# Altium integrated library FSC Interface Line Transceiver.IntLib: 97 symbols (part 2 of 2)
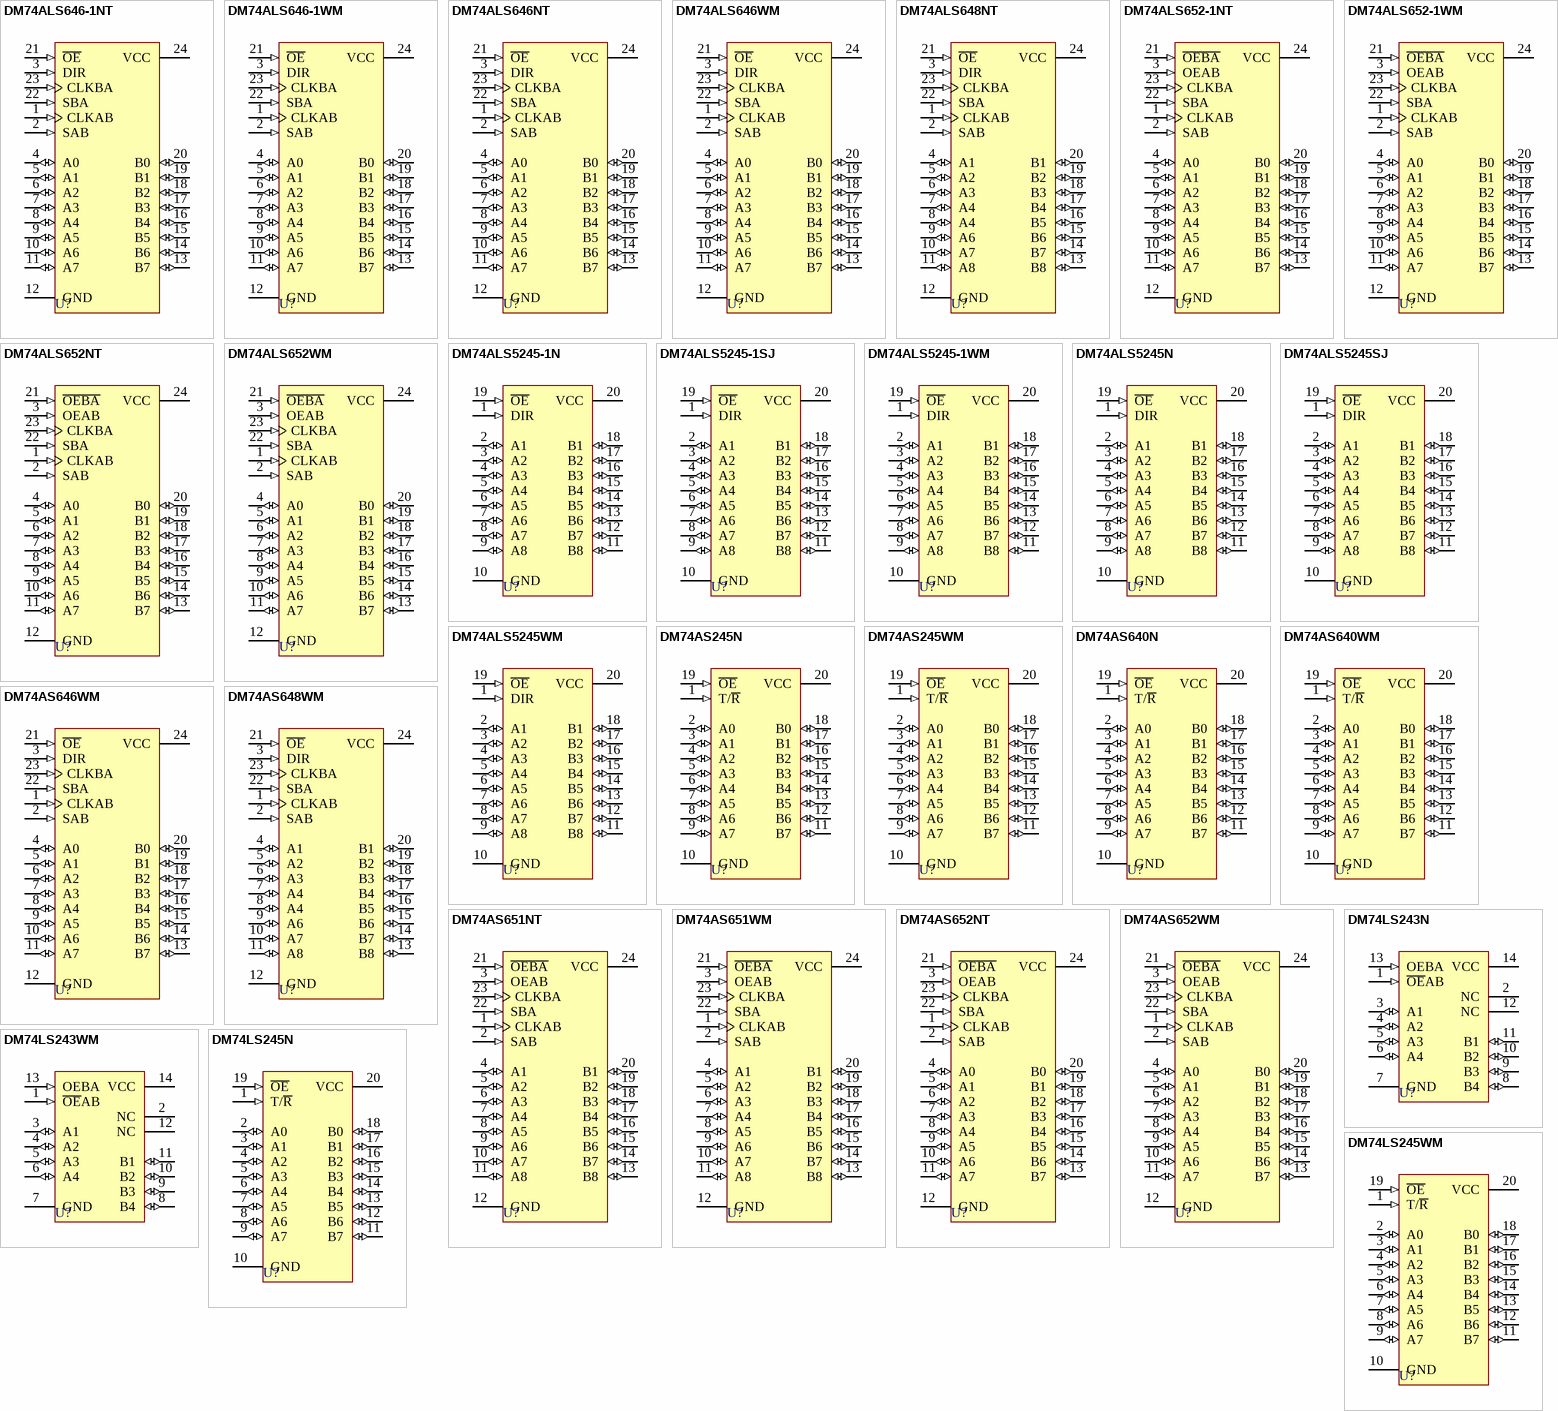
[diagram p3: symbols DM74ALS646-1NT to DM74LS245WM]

## DM74ALS5245N
designator U?
Octal 3-State Transceiver
footprint N20A (DIP; 20 Leads; Row Spacing 7.62 mm; Pitch 2.54 mm)
3D model N20A (DIP; 20 Leads; Row Spacing 7.62 mm; Pitch 2.54 mm)
simulation model 74F245 (SIMCODE)
signal-integrity model DM74ALS5245N
pins: 1 DIR (in), 2 A1 (io), 3 A2 (io), 4 A3 (io), 5 A4 (io), 6 A5 (io), 7 A6 (io), 8 A7 (io), 9 A8 (io), 10 GND (power), 11 B8 (io), 12 B7 (io), 13 B6 (io), 14 B5 (io), 15 B4 (io), 16 B3 (io), 17 B2 (io), 18 B1 (io), 19 ~{OE} (in), 20 VCC (power)

## DM74ALS5245SJ
designator U?
Octal 3-State Transceiver
footprint M20D_N (SOP, 20-Leads, Body 12.6x5.3mm, Pitch 1.27mm, IPC Medium Density)
footprint M20D_L (SOP, 20-Leads, Body 12.6x5.3mm, Pitch 1.27mm, IPC High Density)
footprint M20D_M (SOP, 20-Leads, Body 12.6x5.3mm, Pitch 1.27mm, IPC Low Density)
3D model M20D (20-Pin Small Outline Package 1.27 mm Pitch)
simulation model 74F245 (SIMCODE)
signal-integrity model DM74ALS5245SJ
pins: 1 DIR (in), 2 A1 (io), 3 A2 (io), 4 A3 (io), 5 A4 (io), 6 A5 (io), 7 A6 (io), 8 A7 (io), 9 A8 (io), 10 GND (power), 11 B8 (io), 12 B7 (io), 13 B6 (io), 14 B5 (io), 15 B4 (io), 16 B3 (io), 17 B2 (io), 18 B1 (io), 19 ~{OE} (in), 20 VCC (power)

## DM74ALS5245WM
designator U?
Octal 3-State Transceiver
footprint M20B_N (SOIC, 20-Leads, Body 12.8x7.5mm, Pitch 1.27mm, IPC Medium Density)
footprint M20B_L (SOIC, 20-Leads, Body 12.8x7.5mm, Pitch 1.27mm, IPC High Density)
footprint M20B_M (SOIC, 20-Leads, Body 12.8x7.5mm, Pitch 1.27mm, IPC Low Density)
3D model M20B (20-Pin Small Outline Integrated Circuit 1.27 mm Pitch)
simulation model 74F245 (SIMCODE)
signal-integrity model DM74ALS5245WM
pins: 1 DIR (in), 2 A1 (io), 3 A2 (io), 4 A3 (io), 5 A4 (io), 6 A5 (io), 7 A6 (io), 8 A7 (io), 9 A8 (io), 10 GND (power), 11 B8 (io), 12 B7 (io), 13 B6 (io), 14 B5 (io), 15 B4 (io), 16 B3 (io), 17 B2 (io), 18 B1 (io), 19 ~{OE} (in), 20 VCC (power)

## DM74AS245N
designator U?
Octal Bus Transceiver with 3-State Output
footprint N20A (DIP; 20 Leads; Row Spacing 7.62 mm; Pitch 2.54 mm)
3D model N20A (DIP; 20 Leads; Row Spacing 7.62 mm; Pitch 2.54 mm)
simulation model 74F245 (SIMCODE)
signal-integrity model DM74AS245N
pins: 1 T/~{R} (in), 2 A0 (io), 3 A1 (io), 4 A2 (io), 5 A3 (io), 6 A4 (io), 7 A5 (io), 8 A6 (io), 9 A7 (io), 10 GND (power), 11 B7 (io), 12 B6 (io), 13 B5 (io), 14 B4 (io), 15 B3 (io), 16 B2 (io), 17 B1 (io), 18 B0 (io), 19 ~{OE} (in), 20 VCC (power)

## DM74AS245WM
designator U?
Octal Bus Transceiver with 3-State Output
footprint M20B_N (SOIC, 20-Leads, Body 12.8x7.5mm, Pitch 1.27mm, IPC Medium Density)
footprint M20B_L (SOIC, 20-Leads, Body 12.8x7.5mm, Pitch 1.27mm, IPC High Density)
footprint M20B_M (SOIC, 20-Leads, Body 12.8x7.5mm, Pitch 1.27mm, IPC Low Density)
3D model M20B (20-Pin Small Outline Integrated Circuit 1.27 mm Pitch)
simulation model 74F245 (SIMCODE)
signal-integrity model DM74AS245WM
pins: 1 T/~{R} (in), 2 A0 (io), 3 A1 (io), 4 A2 (io), 5 A3 (io), 6 A4 (io), 7 A5 (io), 8 A6 (io), 9 A7 (io), 10 GND (power), 11 B7 (io), 12 B6 (io), 13 B5 (io), 14 B4 (io), 15 B3 (io), 16 B2 (io), 17 B1 (io), 18 B0 (io), 19 ~{OE} (in), 20 VCC (power)

## DM74AS640N
designator U?
3-State Octal Bus Transceiver
footprint N20A (DIP; 20 Leads; Row Spacing 7.62 mm; Pitch 2.54 mm)
3D model N20A (DIP; 20 Leads; Row Spacing 7.62 mm; Pitch 2.54 mm)
signal-integrity model DM74AS640N
pins: 1 T/~{R} (in), 2 A0 (io), 3 A1 (io), 4 A2 (io), 5 A3 (io), 6 A4 (io), 7 A5 (io), 8 A6 (io), 9 A7 (io), 10 GND (power), 11 B7 (io), 12 B6 (io), 13 B5 (io), 14 B4 (io), 15 B3 (io), 16 B2 (io), 17 B1 (io), 18 B0 (io), 19 ~{OE} (in), 20 VCC (power)

## DM74AS640WM
designator U?
3-State Octal Bus Transceiver
footprint M20B_N (SOIC, 20-Leads, Body 12.8x7.5mm, Pitch 1.27mm, IPC Medium Density)
footprint M20B_L (SOIC, 20-Leads, Body 12.8x7.5mm, Pitch 1.27mm, IPC High Density)
footprint M20B_M (SOIC, 20-Leads, Body 12.8x7.5mm, Pitch 1.27mm, IPC Low Density)
3D model M20B (20-Pin Small Outline Integrated Circuit 1.27 mm Pitch)
signal-integrity model DM74AS640WM
pins: 1 T/~{R} (in), 2 A0 (io), 3 A1 (io), 4 A2 (io), 5 A3 (io), 6 A4 (io), 7 A5 (io), 8 A6 (io), 9 A7 (io), 10 GND (power), 11 B7 (io), 12 B6 (io), 13 B5 (io), 14 B4 (io), 15 B3 (io), 16 B2 (io), 17 B1 (io), 18 B0 (io), 19 ~{OE} (in), 20 VCC (power)

## DM74AS646WM
designator U?
Octal Bus Transceiver and Register
footprint M24B_N (SOIC, 24-Leads, Body 15.4x7.5mm, Pitch 1.27mm, IPC Medium Density)
footprint M24B_L (SOIC, 24-Leads, Body 15.4x7.5mm, Pitch 1.27mm, IPC High Density)
footprint M24B_M (SOIC, 24-Leads, Body 15.4x7.5mm, Pitch 1.27mm, IPC Low Density)
3D model M24B (24-Pin Small Outline Integrated Circuit 1.27 mm Pitch)
signal-integrity model DM74AS646WM
pins: 1 CLKAB (in), 2 SAB (in), 3 DIR (in), 4 A0 (io), 5 A1 (io), 6 A2 (io), 7 A3 (io), 8 A4 (io), 9 A5 (io), 10 A6 (io), 11 A7 (io), 12 GND (power), 13 B7 (io), 14 B6 (io), 15 B5 (io), 16 B4 (io), 17 B3 (io), 18 B2 (io), 19 B1 (io), 20 B0 (io), 21 ~{OE} (in), 22 SBA (in), 23 CLKBA (in), 24 VCC (power)

## DM74AS648WM
designator U?
Octal Bus Transceiver and Register
footprint M24B_N (SOIC, 24-Leads, Body 15.4x7.5mm, Pitch 1.27mm, IPC Medium Density)
footprint M24B_L (SOIC, 24-Leads, Body 15.4x7.5mm, Pitch 1.27mm, IPC High Density)
footprint M24B_M (SOIC, 24-Leads, Body 15.4x7.5mm, Pitch 1.27mm, IPC Low Density)
3D model M24B (24-Pin Small Outline Integrated Circuit 1.27 mm Pitch)
signal-integrity model DM74AS648WM
pins: 1 CLKAB (in), 2 SAB (in), 3 DIR (in), 4 A1 (io), 5 A2 (io), 6 A3 (io), 7 A4 (io), 8 A4 (io), 9 A6 (io), 10 A7 (io), 11 A8 (io), 12 GND (power), 13 B8 (io), 14 B7 (io), 15 B6 (io), 16 B5 (io), 17 B4 (io), 18 B3 (io), 19 B2 (io), 20 B1 (io), 21 ~{OE} (in), 22 SBA (in), 23 CLKBA (in), 24 VCC (power)

## DM74AS651NT
designator U?
Octal Bus Transceiver and Register
footprint N24C (DIP; 24 Leads; Row Spacing 7.62 mm; Pitch 2.54 mm)
3D model N24C (DIP; 24 Leads; Row Spacing 7.62 mm; Pitch 2.54 mm)
signal-integrity model DM74AS651NT
pins: 1 CLKAB (in), 2 SAB (in), 3 OEAB (in), 4 A1 (io), 5 A2 (io), 6 A3 (io), 7 A4 (io), 8 A5 (io), 9 A6 (io), 10 A7 (io), 11 A8 (io), 12 GND (power), 13 B8 (io), 14 B7 (io), 15 B6 (io), 16 B5 (io), 17 B4 (io), 18 B3 (io), 19 B2 (io), 20 B1 (io), 21 ~{OEBA} (in), 22 SBA (in), 23 CLKBA (in), 24 VCC (power)

## DM74AS651WM
designator U?
Octal Bus Transceiver and Register
footprint M24B_N (SOIC, 24-Leads, Body 15.4x7.5mm, Pitch 1.27mm, IPC Medium Density)
footprint M24B_L (SOIC, 24-Leads, Body 15.4x7.5mm, Pitch 1.27mm, IPC High Density)
footprint M24B_M (SOIC, 24-Leads, Body 15.4x7.5mm, Pitch 1.27mm, IPC Low Density)
3D model M24B (24-Pin Small Outline Integrated Circuit 1.27 mm Pitch)
signal-integrity model DM74AS651WM
pins: 1 CLKAB (in), 2 SAB (in), 3 OEAB (in), 4 A1 (io), 5 A2 (io), 6 A3 (io), 7 A4 (io), 8 A5 (io), 9 A6 (io), 10 A7 (io), 11 A8 (io), 12 GND (power), 13 B8 (io), 14 B7 (io), 15 B6 (io), 16 B5 (io), 17 B4 (io), 18 B3 (io), 19 B2 (io), 20 B1 (io), 21 ~{OEBA} (in), 22 SBA (in), 23 CLKBA (in), 24 VCC (power)

## DM74AS652NT
designator U?
Octal Bus Transceiver and Register
footprint N24C (DIP; 24 Leads; Row Spacing 7.62 mm; Pitch 2.54 mm)
3D model N24C (DIP; 24 Leads; Row Spacing 7.62 mm; Pitch 2.54 mm)
signal-integrity model DM74AS652NT
pins: 1 CLKAB (in), 2 SAB (in), 3 OEAB (in), 4 A0 (io), 5 A1 (io), 6 A2 (io), 7 A3 (io), 8 A4 (io), 9 A5 (io), 10 A6 (io), 11 A7 (io), 12 GND (power), 13 B7 (io), 14 B6 (io), 15 B5 (io), 16 B4 (io), 17 B3 (io), 18 B2 (io), 19 B1 (io), 20 B0 (io), 21 ~{OEBA} (in), 22 SBA (in), 23 CLKBA (in), 24 VCC (power)

## DM74AS652WM
designator U?
Octal Bus Transceiver and Register
footprint M24B_N (SOIC, 24-Leads, Body 15.4x7.5mm, Pitch 1.27mm, IPC Medium Density)
footprint M24B_L (SOIC, 24-Leads, Body 15.4x7.5mm, Pitch 1.27mm, IPC High Density)
footprint M24B_M (SOIC, 24-Leads, Body 15.4x7.5mm, Pitch 1.27mm, IPC Low Density)
3D model M24B (24-Pin Small Outline Integrated Circuit 1.27 mm Pitch)
signal-integrity model DM74AS652WM
pins: 1 CLKAB (in), 2 SAB (in), 3 OEAB (in), 4 A0 (io), 5 A1 (io), 6 A2 (io), 7 A3 (io), 8 A4 (io), 9 A5 (io), 10 A6 (io), 11 A7 (io), 12 GND (power), 13 B7 (io), 14 B6 (io), 15 B5 (io), 16 B4 (io), 17 B3 (io), 18 B2 (io), 19 B1 (io), 20 B0 (io), 21 ~{OEBA} (in), 22 SBA (in), 23 CLKBA (in), 24 VCC (power)

## DM74LS243N
designator U?
Quadruple Bus Transceiver
footprint N14A (DIP; 14 Leads; Row Spacing 7.62 mm; Pitch 2.54 mm)
3D model N14A (DIP; 14 Leads; Row Spacing 7.62 mm; Pitch 2.54 mm)
simulation model 74LS243 (SIMCODE)
signal-integrity model DM74LS243N
pins: 1 ~{OE}AB (in), 2 NC, 3 A1 (io), 4 A2 (io), 5 A3 (io), 6 A4 (io), 7 GND (power), 8 B4 (io), 9 B3 (io), 10 B2 (io), 11 B1 (io), 12 NC, 13 OEBA (in), 14 VCC (power)

## DM74LS243WM
designator U?
Quadruple Bus Transceiver
footprint M14B_N (SOIC, 14-Leads, Body 9x7.5mm, Pitch 1.27mm, IPC Medium Density)
footprint M14B_L (SOIC, 14-Leads, Body 9x7.5mm, Pitch 1.27mm, IPC High Density)
footprint M14B_M (SOIC, 14-Leads, Body 9x7.5mm, Pitch 1.27mm, IPC Low Density)
3D model M14B (14-Pin Small Outline Integrated Circuit 1.27 mm Pitch)
simulation model 74LS243 (SIMCODE)
signal-integrity model DM74LS243WM
pins: 1 ~{OE}AB (in), 2 NC, 3 A1 (io), 4 A2 (io), 5 A3 (io), 6 A4 (io), 7 GND (power), 8 B4 (io), 9 B3 (io), 10 B2 (io), 11 B1 (io), 12 NC, 13 OEBA (in), 14 VCC (power)

## DM74LS245N
designator U?
3-State Octal Bus Transceiver
footprint N20A (DIP; 20 Leads; Row Spacing 7.62 mm; Pitch 2.54 mm)
3D model N20A (DIP; 20 Leads; Row Spacing 7.62 mm; Pitch 2.54 mm)
simulation model 74F245 (SIMCODE)
signal-integrity model DM74LS245N
pins: 1 T/~{R} (in), 2 A0 (io), 3 A1 (io), 4 A2 (io), 5 A3 (io), 6 A4 (io), 7 A5 (io), 8 A6 (io), 9 A7 (io), 10 GND (power), 11 B7 (io), 12 B6 (io), 13 B5 (io), 14 B4 (io), 15 B3 (io), 16 B2 (io), 17 B1 (io), 18 B0 (io), 19 ~{OE} (in), 20 VCC (power)

## DM74LS245WM
designator U?
3-State Octal Bus Transceiver
footprint M20B_N (SOIC, 20-Leads, Body 12.8x7.5mm, Pitch 1.27mm, IPC Medium Density)
footprint M20B_L (SOIC, 20-Leads, Body 12.8x7.5mm, Pitch 1.27mm, IPC High Density)
footprint M20B_M (SOIC, 20-Leads, Body 12.8x7.5mm, Pitch 1.27mm, IPC Low Density)
3D model M20B (20-Pin Small Outline Integrated Circuit 1.27 mm Pitch)
simulation model 74F245 (SIMCODE)
signal-integrity model DM74LS245WM
pins: 1 T/~{R} (in), 2 A0 (io), 3 A1 (io), 4 A2 (io), 5 A3 (io), 6 A4 (io), 7 A5 (io), 8 A6 (io), 9 A7 (io), 10 GND (power), 11 B7 (io), 12 B6 (io), 13 B5 (io), 14 B4 (io), 15 B3 (io), 16 B2 (io), 17 B1 (io), 18 B0 (io), 19 ~{OE} (in), 20 VCC (power)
